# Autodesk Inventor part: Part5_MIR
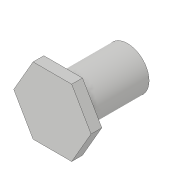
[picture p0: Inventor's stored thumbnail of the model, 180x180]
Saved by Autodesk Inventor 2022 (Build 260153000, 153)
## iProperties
Created: 2008-05
Part Number: Part5_MIR
Material: Generic
Document SubType Name: Modeling
Designer: CADCIM 00
Density: 1 g/cm^3
Appearance: Default
Author: CADCIM
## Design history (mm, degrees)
derived "Part5.ipt"
  sketch "Sketch1"
    geometry: C1 r 2 at (7.12, 11.618) reference
  sketch "Sketch2"
    geometry: L1 (3.598, 0)-(1.799, 3.116) reference; L2 (1.799, 3.116)-(-1.799, 3.116) reference; L3 (-1.799, 3.116)-(-3.598, 0) reference; L4 (-3.598, 0)-(-1.799, -3.116) reference; L5 (-1.799, -3.116)-(1.799, -3.116) reference; L6 (1.799, -3.116)-(3.598, 0) reference; C1 r 2 at (0, 0) reference; 1 further point
    constraints: 1 other
feature "Solid1::Part5.ipt" dims "d0" = 10
tag "TaggingFeature1"
body "Solid1"
